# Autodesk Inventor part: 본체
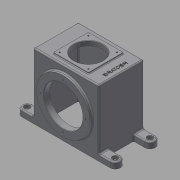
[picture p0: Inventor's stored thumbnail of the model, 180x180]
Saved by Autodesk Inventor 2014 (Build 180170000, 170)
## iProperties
Created: 2016-11
Part Number: 본체
Material: 일반
Document SubType Name: Modeling
Designer: mduedu
Density: 1 g/cm^3
Appearance: 기본값
Author: mduedu
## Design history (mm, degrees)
sketch "스케치1"
  geometry: L1 (-80, 0)-(80, 0); L2 (80, 0)-(80, 160); L3 (80, 160)-(-80, 160); L4 (-80, 160)-(-80, 0); 2 further points
  constraints: 8 end point, 2 parallel, 1 coincident, 1 horizontal, 1 midpoint, 1 perpendicular
  dimensions: "d0" = 160 distance of L2.end L3.end; "d2" = 160 distance of L1.end L2.end
extrude "돌출1" new body sketch "스케치1" stored distance "d3" = 110; taper "d4" = 0 deg
sketch "스케치2"
  geometry: L1 (-80, -55)-(-80, 55) reference; L2 (-80, -55)-(-120, -55); L3 (-120, -55)-(-120, 55); L4 (-120, 55)-(-80, 55); L5 (-80, 55)-(-80, -55); 1 further point
  constraints: 8 end point, 2 parallel, 1 horizontal, 1 perpendicular
  dimensions: "d5" = 40 distance of L1.end L3.end
extrude "돌출2" join sketch "스케치2" distance "d6" = 15; taper "d7" = 0 deg
sketch "스케치3"
  geometry: L1 (80, 55)-(80, -55) reference; L2 (120, -55)-(120, 55) reference; L3 (80, 30)-(120, 30); L4 (120, 30)-(120, -30); L5 (120, -30)-(80, -30); L6 (80, -30)-(80, 30); L7 (-80, -55)-(120, -55) reference; L8 (-80, 55)-(120, 55) reference; 1 further point
  constraints: 8 end point, 2 parallel, 2 point on line, 1 horizontal, 1 perpendicular
  dimensions: "d8" = 25 distance between parallel lines of L5 L7; "d9" = 25 distance between parallel lines of L3 L8 (= d8)
extrude "돌출3" cut sketch "스케치3" stored distance "d10" = 15; taper "d11" = 0 deg
fillet "모깎기1"
fillet "모깎기2"
hole "구멍1" diameter "d14" = 9; stored, may be unused: countersink angle "d18" = 90 deg, drill point angle "d20" = 118 deg; dims "d12" = 10, "d13" = 10, "d15" = 6, "d16" = 14, "d17" = 8, "d19" = 8
fillet "모깎기3" dims "d21" = 3
fillet "모깎기4" dims "d22" = 3
sketch "스케치4"
  geometry: L1 (80, 160)-(-80, 160) reference; L2 (-80, 17.196)-(-80, 160) reference; L3 (80, 17.196)-(80, 160) reference; L4 (-72, 0)-(-72, 152); L5 (-72, 152)-(72, 152); L6 (72, 152)-(72, 0); L7 (-72, 0)-(72, 0); 2 further points
  constraints: 8 end point, 1 coincident, 1 midpoint, 1 perpendicular
  dimensions: "d23" = 8 distance between parallel lines of L5 L1; "d24" = 8 distance between parallel lines of L3 L6 (= d23); "d25" = 8 distance between parallel lines of L2 L4 (= d23)
extrude "돌출4" cut sketch "스케치4" stored distance "d26" = 94; taper "d27" = 0 deg
fillet "모깎기5" dims "d28" = 3
fillet "모깎기6" dims "d29" = 3
fillet "모깎기7" dims "d30" = 3
fillet "모깎기8" dims "d31" = 3
sketch "스케치5"
  geometry: C1 r 65 at (0, 80); 1 further point
  constraints: 1 centre point, 1 vertical alignment
  dimensions: "d32" = 130 diameter of C1; "d33" = 80 distance of C1.centre point (0, 0)
extrude "돌출5" join sketch "스케치5" distance "d34" = 7; taper "d35" = 0 deg
sketch "스케치6"
  geometry: C1 r 35 at (77, 51.5); 2 further points
  constraints: 1 centre point, 1 coincident, 1 vertical alignment
  dimensions: "d36" = 70 diameter of C1; "d77" = 0.5 distance of point (77, 52) point (77, 51.5)
extrude "돌출6" cut sketch "스케치6" stored distance "d37" = 7; taper "d38" = 0 deg
sketch "스케치7"
  geometry: L1 (34.5, 9)-(119.5, 9); L2 (119.5, 9)-(119.5, 94); L3 (119.5, 94)-(34.5, 94); L4 (34.5, 94)-(34.5, 9); L5 (34.5, 9)-(119.5, 94); L6 (119.5, 9)-(34.5, 94); C1 r 35 at (77, 51.5) reference; 2 further points
  constraints: 12 end point, 3 midpoint, 2 parallel, 1 coincident, 1 horizontal, 1 perpendicular
  dimensions: "d39" = 85 distance of L3.end L2.end; "d40" = 85 distance of L1.end L2.end (= d39)
extrude "돌출7" join sketch "스케치7" distance "d41" = 3; taper "d42" = 0 deg
fillet "모깎기9" dims "d43" = 3
fillet "모깎기10" dims "d44" = 2
hole "구멍2" diameter "d47" = 95; stored, may be unused: countersink angle "d51" = 90 deg, drill point angle "d53" = 118 deg; dims "d45" = 10, "d46" = 10, "d48" = 6, "d49" = 14, "d50" = 8, "d52" = 8
chamfer "모따기1" distance "d54" = 1; stored, may be unused: second distance "d55" = 2, angle "d56" = 45 deg
sketch "스케치8"
  geometry: C1 r 65 at (0, 80) reference; C2 r 31.5 at (0, 80); 1 further point
  constraints: 1 centre point, 1 coincident
  dimensions: "d57" = 63 diameter of C2
extrude "돌출8" join sketch "스케치8" distance "d58" = 14; taper "d59" = 0 deg
hole "구멍3" diameter "d62" = 30; stored, may be unused: countersink angle "d66" = 90 deg, drill point angle "d68" = 0 deg; dims "d60" = 10, "d61" = 10, "d63" = 6, "d64" = 47, "d65" = 14, "d67" = 17
fillet "모깎기11" dims "d69" = 3
fillet "모깎기12" dims "d70" = 3
fillet "모깎기13" dims "d71" = 0.5
chamfer "모따기2" distance "d72" = 1; stored, may be unused: second distance "d73" = 2, angle "d74" = 45 deg
fillet "모깎기14" dims "d75" = 3
sketch "스케치9"
  geometry: L1 (157, 0)-(157, 104) reference; L2 (77, 52)-(157, 52); 1 further point
  constraints: 2 end point, 1 midpoint, 1 point on line, 1 other
  dimensions: "d78" = 65 distance of point (142, 52) L2.start
feature "엠보싱1" sketch "스케치9" dims "d79" = 0.5, "d80" = 0
sketch "스케치10"
  geometry: 4 further points
  constraints: 4 other
hole "구멍4" sketch "스케치10" at (0, -55), (55, 0), (-55, 0), (0, 55) diameter "d81" = 3.242; stored, may be unused: countersink angle "d85" = 90 deg, drill point angle "d87" = 120 deg; dims "d82" = 6.6, "d83" = 4, "d84" = 2, "d86" = 8.6
sketch "스케치11"
  geometry: 4 further points
  constraints: 4 other
hole "구멍5" sketch "스케치11" at (42, 86.5), (112, 86.5), (112, 16.5), (42, 16.5) diameter "d88" = 3.242; stored, may be unused: countersink angle "d92" = 90 deg, drill point angle "d94" = 120 deg; dims "d89" = 6.6, "d90" = 4, "d91" = 2, "d93" = 8.6
node "솔리드1"
mirror "대칭1"
mirror "대칭2"
mirror "대칭3"
